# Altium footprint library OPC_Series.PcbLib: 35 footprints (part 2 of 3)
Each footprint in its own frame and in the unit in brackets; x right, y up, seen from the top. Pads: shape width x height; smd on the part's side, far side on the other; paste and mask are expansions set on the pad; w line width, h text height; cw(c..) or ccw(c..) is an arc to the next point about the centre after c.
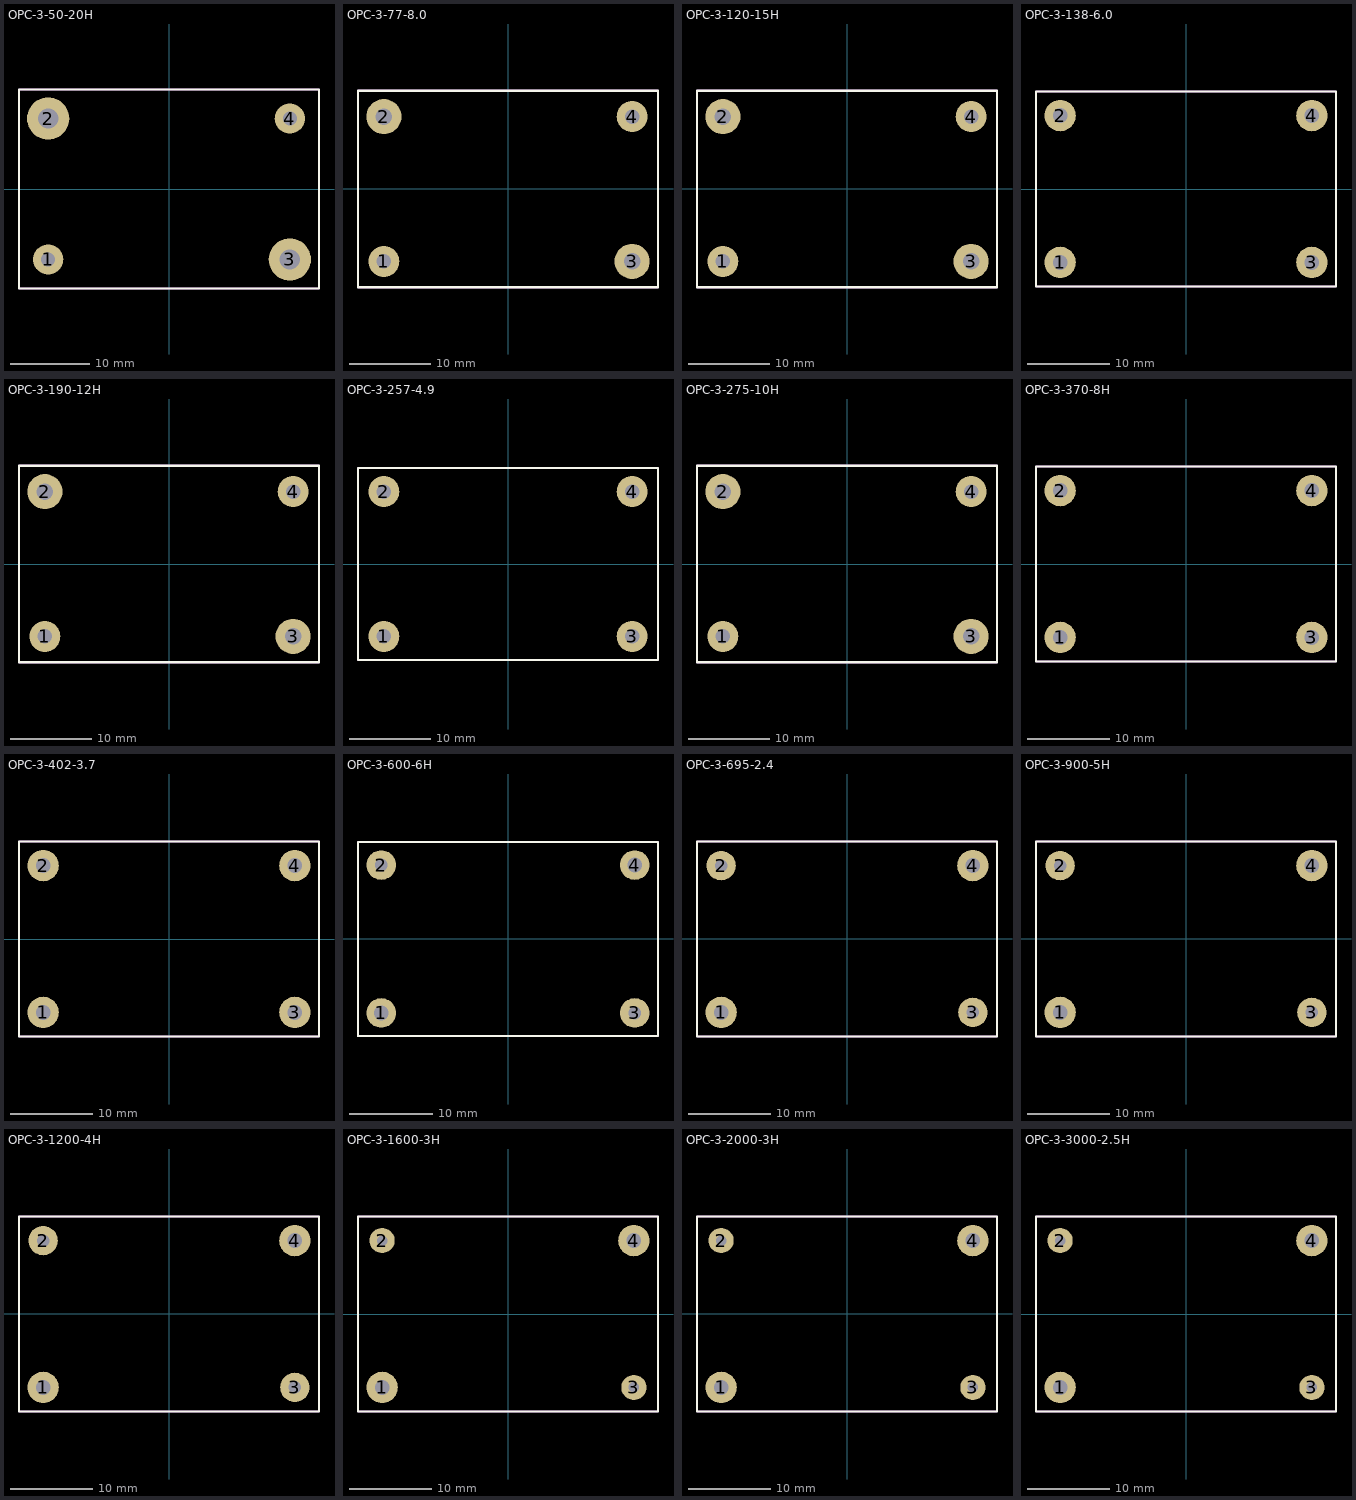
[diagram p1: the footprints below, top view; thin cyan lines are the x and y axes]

## OPC-3-50-20H [mil]
pads (4):
  round 150 hole 70: 1(-600,-350) 4(600,350)
  round 210 hole 100: 2(-600,350) 3(600,-350)
Top Overlay:
  lines w10: -745,110 -745,495 745,495 745,-120 ; -745,120 -745,-495 745,-495 745,-110
Mechanical 29:
  lines w10: -745,110 -745,495 745,495 745,-120 ; -745,120 -745,-495 745,-495 745,-110
  text "'.Designator'" at -1750,-64.85 h400

## OPC-3-77-8.0 [mil]
pads (4):
  round 150 hole 70: 1(-600,-350) 4(600,350)
  round 170 hole 80: 2(-600,350) 3(600,-350)
Top Overlay:
  lines w10: -725,-475 725,-475 725,110 725,475 -725,475 -725,-110 -725,-475
Mechanical 29:
  lines w10: -725,-475 725,-475 725,110 725,475 -725,475 -725,-110 -725,-475
  text "'.Designator'" at -1750,-64.85 h400

## OPC-3-120-15H [mil]
pads (4):
  round 150 hole 70: 1(-600,-350) 4(600,350)
  round 170 hole 80: 2(-600,350) 3(600,-350)
Top Overlay:
  lines w10: -725,-475 -725,-110 -725,475 725,475 725,110 725,-475 -725,-475
Mechanical 29:
  lines w10: -725,-475 -725,-110 -725,475 725,475 725,110 725,-475 -725,-475
  text "'.Designator'" at -1750,-64.85 h400

## OPC-3-138-6.0 [mil]
pads (4):
  round 150 hole 70: 1(-600,-350) 2(-600,350) 3(600,-350) 4(600,350)
Top Overlay:
  lines w10: -715,-465 -715,110 -715,465 715,465 715,110 715,-465 -715,-465
Mechanical 29:
  lines w10: -715,-465 -715,110 -715,465 715,465 715,110 715,-465 -715,-465
  text "'.Designator'" at -1750,-64.85 h400

## OPC-3-190-12H [mil]
pads (4):
  round 150 hole 70: 1(-600,-350) 4(600,350)
  round 170 hole 80: 2(-600,350) 3(600,-350)
Top Overlay:
  lines w10: -725,-475 -725,110 -725,475 725,475 725,110 725,-475 -725,-475
Mechanical 29:
  lines w10: -725,-475 -725,110 -725,475 725,475 725,110 725,-475 -725,-475
  text "'.Designator'" at -1750,-64.85 h400

## OPC-3-257-4.9 [mil]
pads (4):
  round 150 hole 70: 1(-600,-350) 2(-600,350) 3(600,-350) 4(600,350)
Top Overlay:
  lines w10: -725,-465 -725,110 -725,465 725,465 725,110 725,-465 -725,-465
Mechanical 29:
  lines w10: -725,-465 -725,110 -725,465 725,465 725,110 725,-465 -725,-465
  text "'.Designator'" at -1750,-64.85 h400

## OPC-3-275-10H [mil]
pads (4):
  round 150 hole 70: 1(-600,-350) 4(600,350)
  round 170 hole 80: 2(-600,350) 3(600,-350)
Top Overlay:
  lines w10: -725,-475 725,-475 725,110 725,475 -725,475 -725,-475 ; -725,-475 -725,-475
Mechanical 29:
  lines w10: -725,-475 725,-475 725,110 725,475 -725,475 -725,-475 ; -725,-475 -725,-475
  text "'.Designator'" at -1750,-64.85 h400

## OPC-3-370-8H [mil]
pads (4):
  round 150 hole 70: 1(-600,-350) 2(-600,350) 3(600,-350) 4(600,350)
Top Overlay:
  lines w10: -715,110 -715,465 715,465 715,-120 ; -715,120 -715,-465 715,-465 715,-110
Mechanical 29:
  lines w10: -715,110 -715,465 715,465 715,-120 ; -715,120 -715,-465 715,-465 715,-110
  text "'.Designator'" at -1750,-64.85 h400

## OPC-3-402-3.7 [mil]
pads (4):
  round 150 hole 70: 1(-600,-350) 2(-600,350) 3(600,-350) 4(600,350)
Top Overlay:
  lines w10: -715,-465 715,-465 715,110 715,465 -715,465 -715,-110 -715,-465
Mechanical 29:
  lines w10: -715,-465 715,-465 715,110 715,465 -715,465 -715,-110 -715,-465
  text "'.Designator'" at -1750,-64.85 h400

## OPC-3-600-6H [mil]
pads (4):
  round 140 hole 70: 1(-600,-350) 4(600,350)
  round 140 hole 60: 2(-600,350) 3(600,-350)
Top Overlay:
  lines w10: 710,-120 710,460 ; 710,-110 710,-460 -710,-460 ; -710,-460 -710,-110 -710,460 710,460 ; -710,-460 -710,-460 ; 710,460 710,460
Mechanical 29:
  lines w10: 710,-120 710,460 ; 710,-110 710,-460 -710,-460 ; -710,-460 -710,-110 -710,460 710,460 ; -710,-460 -710,-460 ; 710,460 710,460
  text "'.Designator'" at -1750,-64.85 h400

## OPC-3-695-2.4 [mil]
pads (4):
  round 150 hole 70: 1(-600,-350) 4(600,350)
  round 140 hole 60: 2(-600,350) 3(600,-350)
Top Overlay:
  lines w10: 715,-120 715,465 -715,465 -715,-465 715,-465 715,-110
Mechanical 29:
  lines w10: 715,-120 715,465 -715,465 -715,-465 715,-465 715,-110
  text "'.Designator'" at -1750,-64.85 h400

## OPC-3-900-5H [mil]
pads (4):
  round 150 hole 70: 1(-600,-350) 4(600,350)
  round 140 hole 60: 2(-600,350) 3(600,-350)
Top Overlay:
  lines w10: -715,110 -715,465 715,465 715,-120 ; -715,120 -715,-465 715,-465 715,-110
Mechanical 29:
  lines w10: -715,110 -715,465 715,465 715,-120 ; -715,120 -715,-465 715,-465 715,-110
  text "'.Designator'" at -1750,-64.85 h400

## OPC-3-1200-4H [mil]
pads (4):
  round 150 hole 70: 1(-600,-350) 4(600,350)
  round 140 hole 60: 2(-600,350) 3(600,-350)
Top Overlay:
  lines w10: 715,-120 715,465 -715,465 -715,-110 -715,-465 715,-465 715,-110
Mechanical 29:
  lines w10: 715,-120 715,465 -715,465 -715,-110 -715,-465 715,-465 715,-110
  text "'.Designator'" at -1750,-64.85 h400

## OPC-3-1600-3H [mil]
pads (4):
  round 150 hole 70: 1(-600,-350) 4(600,350)
  round 120 hole 50: 2(-600,350) 3(600,-350)
Top Overlay:
  lines w10: -715,-465 -715,110 -715,465 715,465 715,110 715,-465 -715,-465
Mechanical 29:
  lines w10: -715,-465 -715,110 -715,465 715,465 715,110 715,-465 -715,-465
  text "'.Designator'" at -1750,-64.85 h400

## OPC-3-2000-3H [mil]
pads (4):
  round 150 hole 70: 1(-600,-350) 4(600,350)
  round 120 hole 50: 2(-600,350) 3(600,-350)
Top Overlay:
  lines w10: -715,-465 715,-465 715,110 715,465 -715,465 -715,-465
Mechanical 29:
  lines w10: -715,-465 715,-465 715,110 715,465 -715,465 -715,-465
  text "'.Designator'" at -1750,-64.85 h400

## OPC-3-3000-2.5H [mil]
pads (4):
  round 150 hole 70: 1(-600,-350) 4(600,350)
  round 120 hole 50: 2(-600,350) 3(600,-350)
Top Overlay:
  lines w10: -715,-465 -715,110 -715,465 715,465 715,110 715,-465 -715,-465
Mechanical 29:
  lines w10: -715,-465 -715,110 -715,465 715,465 715,110 715,-465 -715,-465
  text "'.Designator'" at -1750,-64.85 h400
